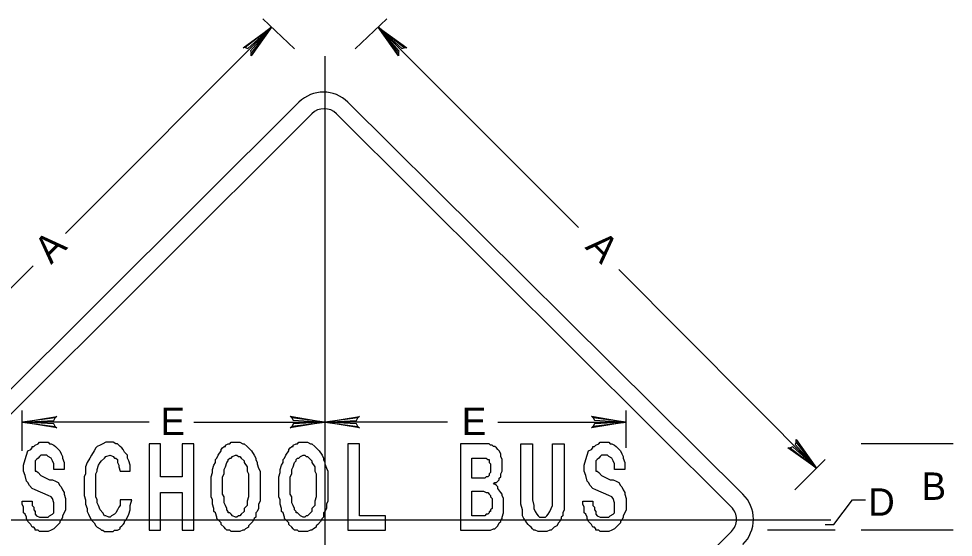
# Model space of a CAD drawing. Extents: x 0.013 to 0.191, y 0.004 to 0.259.
# Drawn here: x 0.0806 to 0.1616, y 0.1557 to 0.2008 of the extents above; entities that cross this region are included whole.
import ezdxf

# ---------------------------------------------------------------- set-up
doc = ezdxf.new("R2010")
doc.units = 0
doc.layers.add('1', color=7, linetype='Continuous')
doc.layers.add('3', color=7, linetype='Continuous')

# ---------------------------------------------------------------- blocks, each defined once
blk = doc.blocks.new('RARROW')
at = {"layer": '3'}
for p, q in [((-2.156, 0.28500000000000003), (-2.2665, 0.384625)), ((-2.2665, 0.384625), (0, 0)), ((0, 0), (-2.2665, -0.379125)), ((-2.156, 0.28500000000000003), (-2.075625, 0.12075)), ((0, 0), (-2.156, 0.28500000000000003)), ((-2.14975, -0.2705), (0, 0)), ((-2.075625, 0.12075), (0, 0)), ((0, 0), (-2.074, -0.108)), ((-2.2665, -0.379125), (-2.14975, -0.2705)), ((-2.074, -0.108), (-2.14975, -0.2705))]:
    blk.add_line(p, q, dxfattribs=at)

msp = doc.modelspace()

# ---------------------------------------------------------------- linework, layer by layer
at = {"layer": '1'}
for p, q in [((0.161625, 0.163875), (0.153625, 0.163875)), ((0.151, 0.15725), (0.068625, 0.15725)), ((0.107125, 0.15725), (0.107125, 0.15725)), ((0.107125, 0.15725), (0.107125, 0.15725)), ((0.151375, 0.15637500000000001), (0.1455, 0.15637500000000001)), ((0.161625, 0.15637500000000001), (0.153625, 0.15637500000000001))]:
    msp.add_line(p, q, dxfattribs=at)
msp.add_lwpolyline([(0.091875, 0.15637500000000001), (0.092875, 0.15637500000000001)], dxfattribs=at)
at = {"layer": '3'}
for p, q in [((0.1045, 0.198125), (0.10175000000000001, 0.20075)), ((0.10975, 0.198125), (0.1125, 0.20075)), ((0.084625, 0.182125), (0.10250000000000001, 0.2)), ((0.129125, 0.182625), (0.11175, 0.2)), ((0.107125, 0.1975), (0.107125, 0.11837500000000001)), ((0.07075000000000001, 0.1595), (0.104875, 0.1935)), ((0.109125, 0.1935), (0.143375, 0.1595)), ((0.07175000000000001, 0.15837500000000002), (0.106, 0.1925)), ((0.108125, 0.1925), (0.142375, 0.15837500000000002)), ((0.08181250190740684, 0.17931250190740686), (0.064375, 0.161875)), ((0.13262260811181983, 0.17899633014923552), (0.14975, 0.16175)), ((0.107125, 0.1685), (0.107125, 0.16675)), ((0.080875, 0.16325), (0.080875, 0.16675)), ((0.13325, 0.1635), (0.13325, 0.16675)), ((0.091875, 0.16575), (0.080875, 0.16575)), ((0.09575, 0.16575), (0.107125, 0.16575)), ((0.11775000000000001, 0.16575), (0.107125, 0.16575)), ((0.122125, 0.16575), (0.13325, 0.16575)), ((0.147875, 0.15987500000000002), (0.1505, 0.1625)), ((0.107125, 0.15687500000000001), (0.107125, 0.154875)), ((0.142375, 0.15625), (0.108125, 0.122))]:
    msp.add_line(p, q, dxfattribs=at)
for points in [[(0.081625, 0.163375), (0.08175, 0.1635), (0.08175, 0.163625), (0.081875, 0.163625), (0.082, 0.16375), (0.08225, 0.163875), (0.082375, 0.164), (0.082625, 0.164), (0.08275, 0.164), (0.082875, 0.164), (0.083125, 0.164), (0.08325, 0.163875), (0.083375, 0.163875), (0.083625, 0.16375), (0.08375, 0.163625), (0.08375, 0.163625), (0.083875, 0.1635)], [(0.09025, 0.1615), (0.09025, 0.162), (0.090125, 0.162375), (0.09, 0.162625), (0.09, 0.162875), (0.08975, 0.163125), (0.089625, 0.163375), (0.0895, 0.1635), (0.089375, 0.163625), (0.08925, 0.16375), (0.089125, 0.163875), (0.089, 0.163875), (0.08875, 0.164), (0.0885, 0.164), (0.088375, 0.164), (0.088125, 0.164), (0.08787500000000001, 0.163875), (0.08762500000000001, 0.16375), (0.08737500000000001, 0.163625), (0.08725000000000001, 0.1635), (0.08712500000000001, 0.16325), (0.08687500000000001, 0.162875), (0.08675000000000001, 0.162625), (0.08650000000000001, 0.16225), (0.08637500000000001, 0.161875), (0.08637500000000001, 0.1615), (0.08637500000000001, 0.16125), (0.08625000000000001, 0.161), (0.08625000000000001, 0.160625), (0.08625000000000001, 0.16025)], [(0.091875, 0.163875), (0.091875, 0.15637500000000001), (0.092875, 0.15637500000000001), (0.092875, 0.15962500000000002), (0.09475, 0.15962500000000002), (0.09475, 0.15637500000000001), (0.09575, 0.15637500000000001), (0.09575, 0.163875), (0.09475, 0.163875), (0.09475, 0.161), (0.092875, 0.161), (0.092875, 0.163875), (0.091875, 0.163875)], [(0.09725, 0.160125), (0.09725, 0.16025), (0.09725, 0.1605), (0.09725, 0.161), (0.097375, 0.161375), (0.097375, 0.161625), (0.0975, 0.162), (0.097625, 0.16225), (0.097625, 0.1625), (0.09775, 0.162625), (0.097875, 0.162875), (0.098125, 0.16325), (0.098125, 0.163375), (0.09825, 0.1635), (0.098375, 0.163625), (0.0985, 0.163625), (0.0985, 0.16375), (0.09875, 0.163875), (0.098875, 0.163875), (0.099, 0.164), (0.099375, 0.164)], [(0.099375, 0.164), (0.0995, 0.164), (0.09975, 0.164), (0.1, 0.163875), (0.100125, 0.163875), (0.100375, 0.163625), (0.1005, 0.1635), (0.10075, 0.16325), (0.101, 0.162875), (0.101125, 0.162625), (0.101125, 0.1625), (0.10125, 0.16225), (0.10125, 0.162125), (0.101375, 0.16175), (0.1015, 0.1615), (0.1015, 0.16125), (0.1015, 0.161), (0.1015, 0.160625), (0.1015, 0.1605), (0.1015, 0.160125)], [(0.10312500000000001, 0.160125), (0.10312500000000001, 0.16025), (0.10312500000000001, 0.1605), (0.10312500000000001, 0.161), (0.10325000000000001, 0.161375), (0.10325000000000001, 0.161625), (0.10337500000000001, 0.162), (0.10350000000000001, 0.16225), (0.10350000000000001, 0.1625), (0.10362500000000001, 0.162625), (0.10375000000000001, 0.162875), (0.10400000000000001, 0.16325), (0.10400000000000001, 0.163375), (0.104125, 0.1635), (0.10425, 0.163625), (0.104375, 0.163625), (0.104375, 0.16375), (0.104625, 0.163875), (0.10475, 0.163875), (0.104875, 0.164), (0.10525, 0.164)], [(0.10525, 0.164), (0.105375, 0.164), (0.105625, 0.164), (0.105875, 0.163875), (0.106, 0.163875), (0.10625, 0.163625), (0.106375, 0.1635), (0.106625, 0.16325), (0.106875, 0.162875), (0.107, 0.162625), (0.107, 0.1625), (0.107125, 0.16225), (0.107125, 0.162125), (0.10725, 0.16175), (0.107375, 0.1615), (0.107375, 0.16125), (0.107375, 0.161), (0.107375, 0.160625), (0.107375, 0.1605), (0.107375, 0.160125)], [(0.109125, 0.163875), (0.109125, 0.15637500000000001), (0.112375, 0.15637500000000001), (0.112375, 0.15762500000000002), (0.110125, 0.15762500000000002), (0.110125, 0.163875), (0.109125, 0.163875)], [(0.121125, 0.163875), (0.11887500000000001, 0.163875), (0.11887500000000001, 0.15637500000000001), (0.121, 0.15637500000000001)], [(0.12175, 0.160375), (0.121875, 0.1605), (0.122, 0.1605), (0.122125, 0.160625), (0.12225, 0.16075), (0.12225, 0.160875), (0.122375, 0.161), (0.122375, 0.16125), (0.1225, 0.1615), (0.1225, 0.161625), (0.1225, 0.16175), (0.1225, 0.16225), (0.1225, 0.1625), (0.122375, 0.16275), (0.122375, 0.162875), (0.122375, 0.162875), (0.122375, 0.163), (0.12225, 0.16325), (0.122125, 0.163375), (0.122, 0.1635), (0.121875, 0.163625), (0.121875, 0.163625), (0.12175, 0.163625), (0.121625, 0.16375), (0.1215, 0.16375), (0.121375, 0.163875), (0.121125, 0.163875)], [(0.124125, 0.15862500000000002), (0.124125, 0.163875), (0.12512500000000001, 0.163875), (0.12512500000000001, 0.159)], [(0.12687500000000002, 0.159), (0.12687500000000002, 0.163875), (0.12787500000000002, 0.163875), (0.12787500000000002, 0.15862500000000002)], [(0.13025, 0.163375), (0.130375, 0.1635), (0.130375, 0.163625), (0.1305, 0.163625), (0.130625, 0.16375), (0.130875, 0.163875), (0.131, 0.164), (0.13125, 0.164), (0.131375, 0.164), (0.1315, 0.164), (0.13175, 0.164), (0.131875, 0.163875), (0.132, 0.163875), (0.13225, 0.16375), (0.132375, 0.163625), (0.132375, 0.163625), (0.1325, 0.1635)], [(0.083625, 0.15837500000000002), (0.083625, 0.1585), (0.083625, 0.15875), (0.0835, 0.15912500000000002), (0.083375, 0.15925), (0.083125, 0.15937500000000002), (0.082, 0.15987500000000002), (0.08175, 0.16), (0.0815, 0.16025), (0.081375, 0.1605), (0.08125, 0.160625), (0.081125, 0.161125), (0.081, 0.1615), (0.081, 0.162), (0.081125, 0.1625), (0.08125, 0.162875), (0.081375, 0.16325), (0.081625, 0.163375)], [(0.083875, 0.1635), (0.084125, 0.16325), (0.08425, 0.163), (0.084375, 0.16275), (0.084375, 0.162625), (0.0845, 0.16225), (0.0845, 0.162), (0.0845, 0.161625), (0.083625, 0.161625)], [(0.13225, 0.15837500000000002), (0.13225, 0.1585), (0.13225, 0.15875), (0.132125, 0.15912500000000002), (0.132, 0.15925), (0.13175, 0.15937500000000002), (0.130625, 0.15987500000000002), (0.130375, 0.16), (0.130125, 0.16025), (0.13, 0.1605), (0.129875, 0.160625), (0.12975, 0.161125), (0.129625, 0.1615), (0.129625, 0.162), (0.12975, 0.1625), (0.129875, 0.162875), (0.13, 0.16325), (0.13025, 0.163375)], [(0.1325, 0.1635), (0.13275, 0.16325), (0.132875, 0.163), (0.133, 0.16275), (0.133, 0.162625), (0.133125, 0.16225), (0.133125, 0.162), (0.133125, 0.161625), (0.13225, 0.161625)], [(0.083625, 0.161625), (0.083625, 0.162125), (0.0835, 0.162375), (0.083375, 0.162625), (0.083375, 0.162625), (0.083125, 0.16275), (0.083, 0.162875), (0.08275, 0.162875), (0.0825, 0.162875), (0.082375, 0.16275), (0.08225, 0.162625), (0.082125, 0.1625), (0.082, 0.162375), (0.082, 0.162125), (0.082, 0.161875)], [(0.08725000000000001, 0.160375), (0.08725000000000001, 0.160625), (0.08725000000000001, 0.161), (0.08725000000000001, 0.16125), (0.08737500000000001, 0.1615), (0.08737500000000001, 0.161625), (0.08750000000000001, 0.162), (0.08762500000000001, 0.16225), (0.08775000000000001, 0.162375), (0.088, 0.162625), (0.088125, 0.16275), (0.0885, 0.162875), (0.0885, 0.162875), (0.08875, 0.16275), (0.08875, 0.16275), (0.088875, 0.162625), (0.089, 0.162625), (0.089125, 0.1625), (0.089125, 0.16225), (0.08925, 0.162), (0.08925, 0.161875), (0.089375, 0.1615)], [(0.09825, 0.16025), (0.09825, 0.160375), (0.09825, 0.1605), (0.09825, 0.16075), (0.09825, 0.161), (0.098375, 0.16125), (0.098375, 0.161375), (0.098375, 0.161625), (0.0985, 0.161875), (0.098625, 0.16225), (0.098625, 0.16225), (0.09875, 0.162375), (0.09875, 0.1625), (0.098875, 0.162625), (0.099, 0.162625), (0.099125, 0.16275), (0.099375, 0.162875), (0.0995, 0.162875)], [(0.0995, 0.162875), (0.0995, 0.162875), (0.099625, 0.16275), (0.09975, 0.16275), (0.099875, 0.162625), (0.100125, 0.162375), (0.100125, 0.16225), (0.100375, 0.161875), (0.100375, 0.1615), (0.1005, 0.16125), (0.1005, 0.160875), (0.1005, 0.160625), (0.1005, 0.160375), (0.1005, 0.16025)], [(0.104125, 0.16025), (0.104125, 0.160375), (0.104125, 0.1605), (0.104125, 0.16075), (0.104125, 0.161), (0.10425, 0.16125), (0.10425, 0.161375), (0.10425, 0.161625), (0.104375, 0.161875), (0.1045, 0.16225), (0.1045, 0.16225), (0.104625, 0.162375), (0.104625, 0.1625), (0.10475, 0.162625), (0.104875, 0.162625), (0.105, 0.16275), (0.10525, 0.162875), (0.105375, 0.162875)], [(0.105375, 0.162875), (0.105375, 0.162875), (0.1055, 0.16275), (0.105625, 0.16275), (0.10575, 0.162625), (0.106, 0.162375), (0.106, 0.16225), (0.10625, 0.161875), (0.10625, 0.1615), (0.106375, 0.16125), (0.106375, 0.160875), (0.106375, 0.160625), (0.106375, 0.160375), (0.106375, 0.16025)], [(0.121, 0.160875), (0.11987500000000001, 0.160875), (0.11987500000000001, 0.162625), (0.121, 0.162625)], [(0.121, 0.162625), (0.121125, 0.162625), (0.12125, 0.1625), (0.121375, 0.1625), (0.121375, 0.162375), (0.121375, 0.16225), (0.1215, 0.162125), (0.1215, 0.161875), (0.1215, 0.161625), (0.1215, 0.161375), (0.121375, 0.16125), (0.121375, 0.161125), (0.12125, 0.161), (0.121125, 0.161), (0.121, 0.160875)], [(0.13225, 0.161625), (0.13225, 0.162125), (0.132125, 0.162375), (0.132, 0.162625), (0.132, 0.162625), (0.13175, 0.16275), (0.131625, 0.162875), (0.131375, 0.162875), (0.131125, 0.162875), (0.131, 0.16275), (0.130875, 0.162625), (0.13075, 0.1625), (0.130625, 0.162375), (0.130625, 0.162125), (0.130625, 0.161875)], [(0.082, 0.161875), (0.082, 0.16175), (0.082, 0.1615), (0.082125, 0.1615), (0.08225, 0.161375), (0.0825, 0.161125), (0.08325, 0.16075), (0.0835, 0.16075), (0.08375, 0.160625), (0.084, 0.1605), (0.084125, 0.16025), (0.08425, 0.160125), (0.084375, 0.15987500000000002), (0.0845, 0.15962500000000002), (0.0845, 0.1595), (0.084625, 0.15912500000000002), (0.084625, 0.15887500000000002), (0.084625, 0.15875), (0.084625, 0.1585), (0.084625, 0.15812500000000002), (0.0845, 0.15787500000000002), (0.0845, 0.15787500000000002)], [(0.089375, 0.1615), (0.09025, 0.1615)], [(0.130625, 0.161875), (0.130625, 0.16175), (0.130625, 0.1615), (0.13075, 0.1615), (0.130875, 0.161375), (0.131125, 0.161125), (0.131875, 0.16075), (0.132125, 0.16075), (0.132375, 0.160625), (0.132625, 0.1605), (0.13275, 0.16025), (0.132875, 0.160125), (0.133, 0.15987500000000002), (0.133125, 0.15962500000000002), (0.133125, 0.1595), (0.13325, 0.15912500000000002), (0.13325, 0.15887500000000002), (0.13325, 0.15875), (0.13325, 0.1585), (0.13325, 0.15812500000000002), (0.133125, 0.15787500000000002), (0.133125, 0.15787500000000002)], [(0.08625000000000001, 0.16025), (0.08625000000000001, 0.15975), (0.08625000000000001, 0.15937500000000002), (0.08637500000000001, 0.159), (0.08637500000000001, 0.15862500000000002), (0.08650000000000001, 0.15825), (0.08650000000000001, 0.158), (0.08662500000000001, 0.15775), (0.08675000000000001, 0.1575), (0.08687500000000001, 0.15725), (0.08712500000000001, 0.157), (0.08725000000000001, 0.15675), (0.08737500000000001, 0.15662500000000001), (0.08737500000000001, 0.15662500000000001), (0.08762500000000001, 0.1565), (0.08775000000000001, 0.15637500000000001), (0.08787500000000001, 0.15637500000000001), (0.088, 0.15625), (0.08825, 0.15625), (0.0885, 0.15625), (0.08875, 0.15625), (0.088875, 0.15637500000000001), (0.089125, 0.15637500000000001), (0.089125, 0.15637500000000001), (0.089375, 0.1565), (0.089375, 0.15662500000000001), (0.0895, 0.15675), (0.089625, 0.15687500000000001), (0.08975, 0.157), (0.08975, 0.15712500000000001), (0.089875, 0.15725), (0.09, 0.1575), (0.090125, 0.15775), (0.09025, 0.15812500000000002), (0.09025, 0.1585), (0.090375, 0.159)], [(0.089375, 0.159), (0.089375, 0.1585), (0.08925, 0.15837500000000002), (0.089125, 0.15812500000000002), (0.089, 0.15787500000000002), (0.088875, 0.15775), (0.088625, 0.15762500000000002), (0.0885, 0.1575), (0.088375, 0.1575), (0.088125, 0.15762500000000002), (0.088, 0.15762500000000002), (0.08787500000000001, 0.15787500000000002), (0.08762500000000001, 0.15812500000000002), (0.08750000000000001, 0.1585), (0.08737500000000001, 0.15875), (0.08737500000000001, 0.159), (0.08725000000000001, 0.15925), (0.08725000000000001, 0.1595), (0.08725000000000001, 0.15987500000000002), (0.08725000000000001, 0.16), (0.08725000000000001, 0.160375), (0.08725000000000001, 0.160375)], [(0.1015, 0.160125), (0.1015, 0.15962500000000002), (0.1015, 0.15912500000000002), (0.1015, 0.15887500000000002), (0.101375, 0.15862500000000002), (0.101375, 0.15825), (0.10125, 0.158), (0.101125, 0.15787500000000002), (0.101125, 0.1575), (0.101, 0.15737500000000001), (0.100875, 0.15712500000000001), (0.100625, 0.15687500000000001), (0.1005, 0.15675), (0.1005, 0.15662500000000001), (0.10025, 0.1565), (0.100125, 0.15637500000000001), (0.1, 0.15637500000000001), (0.09975, 0.15625), (0.0995, 0.15625), (0.0995, 0.15625), (0.09925, 0.15625), (0.099, 0.15625), (0.098875, 0.15637500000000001), (0.09875, 0.15637500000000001), (0.098625, 0.15637500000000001), (0.0985, 0.1565), (0.0985, 0.1565), (0.098375, 0.15662500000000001), (0.098125, 0.15687500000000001), (0.098125, 0.157), (0.09775, 0.15737500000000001), (0.09775, 0.1575), (0.097625, 0.15787500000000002), (0.0975, 0.158), (0.0975, 0.15825), (0.097375, 0.15862500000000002), (0.097375, 0.15875), (0.097375, 0.159), (0.09725, 0.15925), (0.09725, 0.15962500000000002), (0.09725, 0.15987500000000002), (0.09725, 0.160125)], [(0.0995, 0.1575), (0.099375, 0.1575), (0.099125, 0.15762500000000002), (0.099, 0.15775), (0.098875, 0.15787500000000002), (0.09875, 0.15787500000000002), (0.09875, 0.158), (0.098625, 0.15812500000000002), (0.098625, 0.15825), (0.0985, 0.1585), (0.098375, 0.15875), (0.098375, 0.159), (0.098375, 0.15925), (0.09825, 0.1595), (0.09825, 0.15962500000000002), (0.09825, 0.15987500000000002), (0.09825, 0.160125), (0.09825, 0.16025)], [(0.1005, 0.16025), (0.1005, 0.160125), (0.1005, 0.15975), (0.1005, 0.1595), (0.1005, 0.15925), (0.100375, 0.15887500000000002), (0.100375, 0.1585), (0.100125, 0.15825), (0.100125, 0.158), (0.099875, 0.15775), (0.09975, 0.15762500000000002), (0.099625, 0.15762500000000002), (0.0995, 0.1575), (0.0995, 0.1575)], [(0.107375, 0.160125), (0.107375, 0.15962500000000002), (0.107375, 0.15912500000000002), (0.107375, 0.15887500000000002), (0.10725, 0.15862500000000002), (0.10725, 0.15825), (0.107125, 0.158), (0.107, 0.15787500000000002), (0.107, 0.1575), (0.106875, 0.15737500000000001), (0.10675, 0.15712500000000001), (0.1065, 0.15687500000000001), (0.106375, 0.15675), (0.106375, 0.15662500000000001), (0.106125, 0.1565), (0.106, 0.15637500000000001), (0.105875, 0.15637500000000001), (0.105625, 0.15625), (0.105375, 0.15625), (0.105375, 0.15625), (0.105125, 0.15625), (0.104875, 0.15625), (0.10475, 0.15637500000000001), (0.104625, 0.15637500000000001), (0.1045, 0.15637500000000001), (0.104375, 0.1565), (0.104375, 0.1565), (0.10425, 0.15662500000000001), (0.10400000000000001, 0.15687500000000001), (0.10400000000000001, 0.157), (0.10362500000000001, 0.15737500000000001), (0.10362500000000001, 0.1575), (0.10350000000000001, 0.15787500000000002), (0.10337500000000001, 0.158), (0.10337500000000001, 0.15825), (0.10325000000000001, 0.15862500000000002), (0.10325000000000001, 0.15875), (0.10325000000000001, 0.159), (0.10312500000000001, 0.15925), (0.10312500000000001, 0.15962500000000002), (0.10312500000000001, 0.15987500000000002), (0.10312500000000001, 0.160125)], [(0.105375, 0.1575), (0.10525, 0.1575), (0.105, 0.15762500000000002), (0.104875, 0.15775), (0.10475, 0.15787500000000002), (0.104625, 0.15787500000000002), (0.104625, 0.158), (0.1045, 0.15812500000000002), (0.1045, 0.15825), (0.104375, 0.1585), (0.10425, 0.15875), (0.10425, 0.159), (0.10425, 0.15925), (0.104125, 0.1595), (0.104125, 0.15962500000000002), (0.104125, 0.15987500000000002), (0.104125, 0.160125), (0.104125, 0.16025)], [(0.106375, 0.16025), (0.106375, 0.160125), (0.106375, 0.15975), (0.106375, 0.1595), (0.106375, 0.15925), (0.10625, 0.15887500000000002), (0.10625, 0.1585), (0.106, 0.15825), (0.106, 0.158), (0.10575, 0.15775), (0.105625, 0.15762500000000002), (0.1055, 0.15762500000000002), (0.105375, 0.1575), (0.105375, 0.1575)], [(0.120875, 0.15762500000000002), (0.11987500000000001, 0.15762500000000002), (0.11987500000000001, 0.15975), (0.120875, 0.15975)], [(0.120875, 0.15975), (0.121125, 0.15962500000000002), (0.12125, 0.15962500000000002), (0.121375, 0.1595), (0.121375, 0.1595), (0.1215, 0.15937500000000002), (0.1215, 0.15925), (0.121625, 0.15912500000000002), (0.121625, 0.159), (0.121625, 0.15887500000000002), (0.121625, 0.15862500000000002), (0.121625, 0.1585), (0.121625, 0.15825), (0.1215, 0.15812500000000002), (0.1215, 0.158), (0.121375, 0.158), (0.121375, 0.15787500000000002), (0.12125, 0.15775), (0.121125, 0.15775), (0.121, 0.15762500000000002), (0.120875, 0.15762500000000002)], [(0.121, 0.15637500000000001), (0.121125, 0.15637500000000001), (0.1215, 0.15637500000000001), (0.12175, 0.1565), (0.121875, 0.1565), (0.122, 0.15662500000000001), (0.122, 0.15662500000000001), (0.122125, 0.15675), (0.12225, 0.157), (0.122375, 0.15712500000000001), (0.122375, 0.15725), (0.1225, 0.15737500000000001), (0.1225, 0.1575), (0.122625, 0.15787500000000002), (0.122625, 0.15812500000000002), (0.122625, 0.15825), (0.122625, 0.15862500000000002), (0.122625, 0.159), (0.122625, 0.15912500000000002), (0.1225, 0.15937500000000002), (0.1225, 0.1595), (0.122375, 0.15962500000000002), (0.122125, 0.16), (0.122125, 0.160125), (0.122, 0.16025), (0.121875, 0.160375), (0.12175, 0.160375)], [(0.08125, 0.15737500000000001), (0.08125, 0.1575), (0.081125, 0.15775), (0.081, 0.15787500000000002), (0.081, 0.158), (0.081, 0.15812500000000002), (0.081, 0.15837500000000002), (0.080875, 0.15862500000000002), (0.080875, 0.15887500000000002)], [(0.080875, 0.15887500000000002), (0.08175, 0.15887500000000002), (0.08175, 0.15875)], [(0.090375, 0.159), (0.089375, 0.159)], [(0.12512500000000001, 0.159), (0.12525, 0.1585), (0.12525, 0.15825), (0.12537500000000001, 0.158), (0.1255, 0.15775), (0.12562500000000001, 0.15762500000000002), (0.12575, 0.1575), (0.126, 0.1575), (0.126, 0.1575), (0.12625, 0.1575), (0.12637500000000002, 0.15762500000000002), (0.1265, 0.15775), (0.12662500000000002, 0.158), (0.12675, 0.15825), (0.12687500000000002, 0.1585), (0.12687500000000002, 0.159)], [(0.129875, 0.15737500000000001), (0.129875, 0.1575), (0.12975, 0.15775), (0.129625, 0.15787500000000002), (0.129625, 0.158), (0.129625, 0.15812500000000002), (0.129625, 0.15837500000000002), (0.1295, 0.15862500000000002), (0.1295, 0.15887500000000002)], [(0.1295, 0.15887500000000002), (0.130375, 0.15887500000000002), (0.130375, 0.15875)], [(0.1505, 0.15687500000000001), (0.15125, 0.15687500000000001), (0.152875, 0.159), (0.154, 0.159)], [(0.08175, 0.15875), (0.08175, 0.1585), (0.081875, 0.15837500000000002), (0.081875, 0.15812500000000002), (0.082, 0.158), (0.082, 0.15775), (0.082125, 0.15762500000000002), (0.082375, 0.1575), (0.082625, 0.1575), (0.08275, 0.1575), (0.082875, 0.1575), (0.083125, 0.1575), (0.08325, 0.15762500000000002)], [(0.08325, 0.15762500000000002), (0.0835, 0.15775), (0.083625, 0.15787500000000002), (0.083625, 0.15812500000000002), (0.083625, 0.15837500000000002)], [(0.12787500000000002, 0.15862500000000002), (0.12787500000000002, 0.15812500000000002), (0.12775, 0.15787500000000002), (0.12775, 0.15762500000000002), (0.12762500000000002, 0.1575), (0.12762500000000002, 0.15737500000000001), (0.1275, 0.15712500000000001), (0.12737500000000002, 0.157), (0.12725, 0.15675), (0.127, 0.15662500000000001), (0.12687500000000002, 0.1565), (0.12675, 0.15637500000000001), (0.12662500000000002, 0.15637500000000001), (0.12637500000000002, 0.15625), (0.12612500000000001, 0.15625), (0.12587500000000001, 0.15625), (0.12562500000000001, 0.15625), (0.12537500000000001, 0.15637500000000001), (0.12525, 0.15637500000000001), (0.12525, 0.15637500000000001), (0.12512500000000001, 0.1565), (0.125, 0.15662500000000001), (0.124875, 0.15675), (0.12475, 0.15687500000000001), (0.124625, 0.157), (0.1245, 0.15725), (0.124375, 0.15737500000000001), (0.12425, 0.15762500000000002), (0.12425, 0.15787500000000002), (0.12425, 0.15812500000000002), (0.124125, 0.15862500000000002)], [(0.130375, 0.15875), (0.130375, 0.1585), (0.1305, 0.15837500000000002), (0.1305, 0.15812500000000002), (0.130625, 0.158), (0.130625, 0.15775), (0.13075, 0.15762500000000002), (0.131, 0.1575), (0.13125, 0.1575), (0.131375, 0.1575), (0.1315, 0.1575), (0.13175, 0.1575), (0.131875, 0.15762500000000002)], [(0.131875, 0.15762500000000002), (0.132125, 0.15775), (0.13225, 0.15787500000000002), (0.13225, 0.15812500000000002), (0.13225, 0.15837500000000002)], [(0.0845, 0.15787500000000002), (0.084375, 0.15762500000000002), (0.084375, 0.1575), (0.08425, 0.15725), (0.084125, 0.15712500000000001), (0.084125, 0.157), (0.084, 0.15687500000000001), (0.083875, 0.15675), (0.08375, 0.15662500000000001), (0.083625, 0.1565), (0.083375, 0.15637500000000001), (0.083375, 0.15637500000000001), (0.083125, 0.15625), (0.082875, 0.15625), (0.08275, 0.15625), (0.082625, 0.15625), (0.082375, 0.15625), (0.08225, 0.15637500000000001), (0.082125, 0.15637500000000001), (0.082, 0.15637500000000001), (0.082, 0.1565), (0.081875, 0.15662500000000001), (0.08175, 0.15662500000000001), (0.081625, 0.15687500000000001), (0.081375, 0.15712500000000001), (0.08125, 0.15737500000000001)], [(0.133125, 0.15787500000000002), (0.133, 0.15762500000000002), (0.133, 0.1575), (0.132875, 0.15725), (0.13275, 0.15712500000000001), (0.13275, 0.157), (0.132625, 0.15687500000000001), (0.1325, 0.15675), (0.132375, 0.15662500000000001), (0.13225, 0.1565), (0.132, 0.15637500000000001), (0.132, 0.15637500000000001), (0.13175, 0.15625), (0.1315, 0.15625), (0.131375, 0.15625), (0.13125, 0.15625), (0.131, 0.15625), (0.130875, 0.15637500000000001), (0.13075, 0.15637500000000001), (0.130625, 0.15637500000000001), (0.130625, 0.1565), (0.1305, 0.15662500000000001), (0.130375, 0.15662500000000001), (0.13025, 0.15687500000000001), (0.13, 0.15712500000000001), (0.129875, 0.15737500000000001)]]:
    msp.add_lwpolyline(points, dxfattribs=at)
for centre, radius, start, end in [((0.10700000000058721, 0.19137217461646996), 0.0030072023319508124, 45.03806666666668, 134.96193611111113), ((0.10706249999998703, 0.19143608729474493), 0.001503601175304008, 45.03806666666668, 134.96193611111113), ((0.14120663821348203, 0.15731249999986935), 0.0030800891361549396, 314.74826388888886, 45.25173888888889), ((0.141321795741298, 0.15731249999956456), 0.0014960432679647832, 314.7482611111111, 45.251736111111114)]:
    msp.add_arc(centre, radius, start, end, dxfattribs=at)

# ---------------------------------------------------------------- block references
at = {"layer": '3', "xscale": 0.0013236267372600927}
for p, yscale, rotation in [((0.10250000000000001, 0.2), 0.001309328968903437, 45.093773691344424), ((0.11175, 0.2), 0.001309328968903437, 134.90622630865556), ((0.080875, 0.16575), 0.001309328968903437, 180), ((0.107125, 0.16575), 0.001309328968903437, 180), ((0.14975, 0.16175), 0.0013093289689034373, -45.09377369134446)]:
    msp.add_blockref('RARROW', p, dxfattribs=dict(at, yscale=yscale, rotation=rotation))
at = {"layer": '3', "xscale": 0.0013236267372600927, "yscale": 0.001309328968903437}
for p in [(0.107125, 0.16575), (0.13325, 0.16575)]:
    msp.add_blockref('RARROW', p, dxfattribs=at)

# ---------------------------------------------------------------- texts
at = {"layer": '1'}
for s, p in [('B', (0.15887500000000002, 0.159)), ('D', (0.15425, 0.15762500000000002))]:
    msp.add_text(s, height=0.0023752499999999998, dxfattribs=at).set_placement(p)
at = {"layer": '3'}
for rotation, p in [(45.093775, (0.083375, 0.179375)), (314.906225, (0.129625, 0.180875))]:
    msp.add_text('A', height=0.0023752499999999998, rotation=rotation, dxfattribs=at).set_placement(p)
for p in [(0.092875, 0.164625), (0.11900000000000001, 0.164625)]:
    msp.add_text('E ', height=0.0023752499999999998, dxfattribs=at).set_placement(p)

doc.saveas('drawing.dxf')
